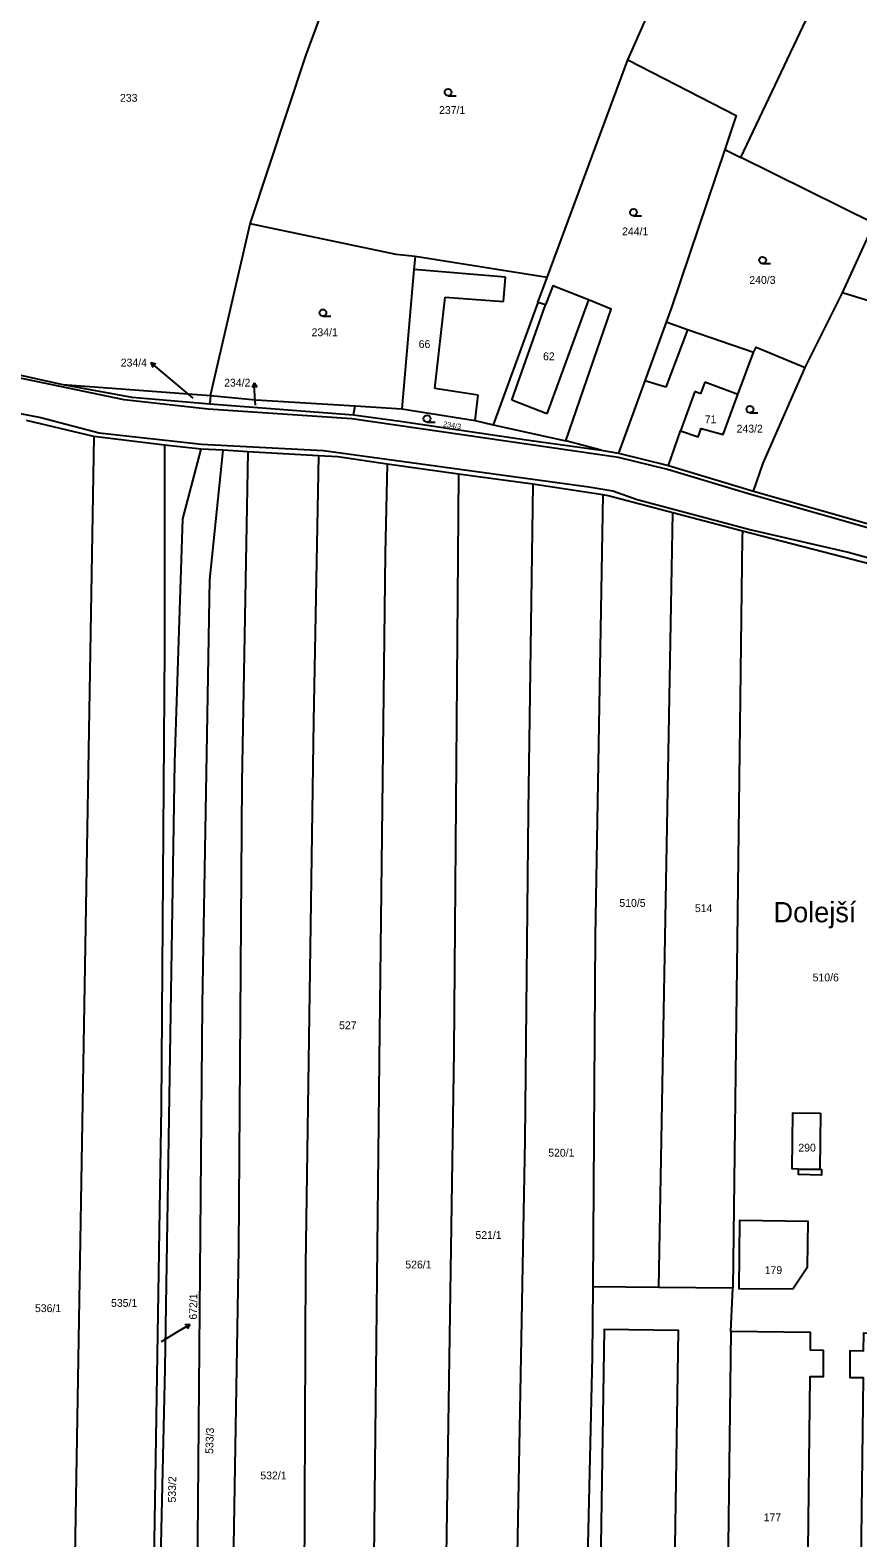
# Model space of a CAD drawing. Extents: x -747333 to -743907, y -1134120 to -1130051.
# Drawn here: x -746642.5 to -746462.8, y -1132539.7 to -1132212.3 of the extents above; entities that cross this region are included whole.
import ezdxf

# ---------------------------------------------------------------- set-up
doc = ezdxf.new("R2010")
doc.units = 0
for name, color, linetype in [('Hranice parcel', 7, 'Continuous'), ('Parcelní čísla', 7, 'Continuous'), ('Pop  PČ popisy', 7, 'Continuous'), ('Vnitřní kresba', 7, 'Continuous'), ('Značky kultur', 7, 'Continuous')]:
    doc.layers.add(name, color=color, linetype=linetype)

msp = doc.modelspace()

# ---------------------------------------------------------------- linework, layer by layer
at = {"layer": 'Hranice parcel'}
for p, q in [((-746512.76, -1132218.71), (-746508.81, -1132209.8)), ((-746530.27, -1132265.98), (-746512.76, -1132218.71)), ((-746491.71, -1132238.23), (-746488.24, -1132239.95)), ((-746459.31, -1132254.28), (-746488.24, -1132239.95)), ((-746603.33, -1132291.63), (-746594.73, -1132254.38)), ((-746466.16, -1132269.31), (-746459.31, -1132254.28)), ((-746530.27, -1132265.98), (-746558.92, -1132261.48)), ((-746532.26, -1132271.42), (-746530.27, -1132265.98)), ((-746532.26, -1132271.42), (-746541.97, -1132298.02)), ((-746474.28, -1132285.54), (-746466.16, -1132269.31)), ((-746438.16, -1132278.12), (-746466.16, -1132269.31)), ((-746488.87, -1132291.4), (-746485.44, -1132282.28)), ((-746635.38, -1132289.23), (-746603.33, -1132291.63)), ((-746603.33, -1132291.63), (-746603.47, -1132293.48)), ((-746603.47, -1132293.48), (-746572.31, -1132295.81)), ((-746572.31, -1132295.81), (-746571.94, -1132293.89)), ((-746571.94, -1132293.89), (-746561.85, -1132294.55)), ((-746628.68, -1132300.58), (-746643.27, -1132297.04)), ((-746541.97, -1132298.02), (-746526.21, -1132301.5)), ((-746613.37, -1132302.42), (-746628.68, -1132300.58)), ((-746518.52, -1132303.5), (-746526.21, -1132301.5)), ((-746503.94, -1132306.81), (-746501.31, -1132299.32)), ((-746605.37, -1132303.28), (-746613.37, -1132302.42)), ((-746600.59, -1132303.55), (-746605.37, -1132303.28)), ((-746595.23, -1132303.86), (-746600.59, -1132303.55)), ((-746579.9, -1132304.75), (-746595.23, -1132303.86)), ((-746518.52, -1132303.5), (-746514.75, -1132304.17)), ((-746514.75, -1132304.17), (-746503.94, -1132306.81)), ((-746549.55, -1132308.74), (-746564.99, -1132306.52)), ((-746503.94, -1132306.81), (-746485.44, -1132312.39)), ((-746533.39, -1132310.87), (-746549.55, -1132308.74)), ((-746518.2, -1132313.24), (-746533.39, -1132310.87)), ((-746506, -1132485.37), (-746503.02, -1132317.1)), ((-746487.88, -1132321.09), (-746503.02, -1132317.1)), ((-746487.88, -1132321.09), (-746487.9, -1132322.49)), ((-746448.07, -1132331.38), (-746487.88, -1132321.09)), ((-746487.9, -1132322.49), (-746489.99, -1132485.51)), ((-746506, -1132485.37), (-746520.37, -1132485.24)), ((-746489.99, -1132485.51), (-746506, -1132485.37)), ((-746490.36, -1132494.89), (-746489.99, -1132485.51)), ((-746490.36, -1132494.89), (-746491.44, -1132579.84))]:
    msp.add_line(p, q, dxfattribs=at)
for points in [[(-746488.24, -1132239.95), (-746463.28, -1132187.24), (-746474.43, -1132179.05), (-746468.85, -1132167.8)], [(-746594.73, -1132254.38), (-746582.55, -1132217.69), (-746573.08, -1132191.94)], [(-746512.76, -1132218.71), (-746489.23, -1132230.86), (-746491.71, -1132238.23)], [(-746491.71, -1132238.23), (-746503.25, -1132272.52), (-746504.41, -1132275.72)], [(-746705.52, -1132254.75), (-746705.52, -1132261.75), (-746702.56, -1132266.68), (-746651.51, -1132285.68), (-746635.38, -1132289.23)], [(-746558.92, -1132261.48), (-746563.06, -1132261.04), (-746594.73, -1132254.38)], [(-746558.92, -1132261.48), (-746559.21, -1132264.29), (-746561.85, -1132294.55)], [(-746526.21, -1132301.5), (-746516.36, -1132272.86), (-746521.29, -1132270.9), (-746529.01, -1132267.83), (-746530.64, -1132271.97), (-746532.26, -1132271.42)], [(-746504.41, -1132275.72), (-746509.03, -1132288.43), (-746514.75, -1132304.17)], [(-746485.44, -1132282.28), (-746499.8, -1132277.41), (-746504.41, -1132275.72)], [(-746485.44, -1132282.28), (-746484.89, -1132281.12), (-746474.28, -1132285.54)], [(-746485.44, -1132312.39), (-746483.4, -1132306.31), (-746474.28, -1132285.54)], [(-746635.38, -1132289.23), (-746620.4, -1132292.04), (-746603.47, -1132293.48)], [(-746603.33, -1132291.63), (-746593.54, -1132292.56), (-746571.94, -1132293.89)], [(-746501.31, -1132299.32), (-746497.49, -1132300.63), (-746496.87, -1132298.83), (-746492.06, -1132300.12), (-746488.87, -1132291.4)], [(-746561.85, -1132294.55), (-746545.91, -1132297.08), (-746541.97, -1132298.02)], [(-746572.31, -1132295.81), (-746562.17, -1132297.22), (-746534.28, -1132301.35), (-746518.52, -1132303.5)], [(-746628.68, -1132300.58), (-746631.28, -1132453.79), (-746633.28, -1132573.72), (-746635.22, -1132678.03)], [(-746613.37, -1132302.42), (-746613.37, -1132346.68), (-746614.08, -1132446.06), (-746615.66, -1132545), (-746618.65, -1132675.35)], [(-746617.07, -1132675.21), (-746613.21, -1132502.87), (-746611.08, -1132371.37), (-746609.37, -1132318.4), (-746605.37, -1132303.28)], [(-746608.92, -1132673.97), (-746606.11, -1132540.09), (-746605.1, -1132423.88), (-746603.53, -1132331.66), (-746600.59, -1132303.55)], [(-746595.23, -1132303.86), (-746596.54, -1132375.65), (-746597.26, -1132477.01), (-746599.26, -1132593.08), (-746600.75, -1132672.72)], [(-746579.9, -1132304.75), (-746580.99, -1132362.37), (-746582.7, -1132480.44), (-746582.99, -1132549.96)], [(-746564.99, -1132306.52), (-746575.68, -1132304.99), (-746579.9, -1132304.75)], [(-746564.99, -1132306.52), (-746565.43, -1132325.98), (-746566.71, -1132436.04), (-746568.01, -1132557.67)], [(-746549.55, -1132308.74), (-746550.51, -1132434.05), (-746552.94, -1132591.21), (-746553.66, -1132645.75), (-746554.56, -1132665.67)], [(-746533.39, -1132310.87), (-746534.4, -1132381.92), (-746535.13, -1132453.3), (-746537.98, -1132610.05), (-746539.11, -1132663.31)], [(-746518.2, -1132313.24), (-746519.81, -1132409.04), (-746520.37, -1132485.24)], [(-746503.02, -1132317.1), (-746517.02, -1132313.41), (-746518.2, -1132313.24)], [(-746485.44, -1132312.39), (-746451.58, -1132322.02), (-746446.14, -1132322.78), (-746443.16, -1132323.2), (-746427.94, -1132325.8)], [(-746470.9, -1132447.53), (-746471.04, -1132459.69), (-746470.74, -1132459.72), (-746470.7, -1132460.94), (-746475.69, -1132460.82), (-746475.68, -1132459.65), (-746477.09, -1132459.62), (-746476.95, -1132447.46), (-746470.9, -1132447.53)], [(-746476.94, -1132485.69), (-746473.77, -1132480.86), (-746473.64, -1132471.05), (-746488.48, -1132470.84), (-746488.65, -1132485.59), (-746476.94, -1132485.69)], [(-746520.37, -1132485.24), (-746520.49, -1132500.34), (-746523.05, -1132610.33)], [(-746519.46, -1132597.46), (-746503.32, -1132597.69), (-746501.74, -1132494.74), (-746517.87, -1132494.47), (-746519.46, -1132597.46)], [(-746491.44, -1132579.84), (-746474.02, -1132580.06), (-746473.18, -1132504.68), (-746470.3, -1132504.71), (-746470.29, -1132499.03), (-746473.11, -1132499), (-746473.07, -1132495.14), (-746490.36, -1132494.89)], [(-746444.3, -1132495.53), (-746461.6, -1132495.32), (-746461.63, -1132499.17), (-746464.54, -1132499.14), (-746464.56, -1132504.89), (-746461.68, -1132504.91), (-746462.63, -1132580.24), (-746445.35, -1132580.44)]]:
    msp.add_lwpolyline(points, dxfattribs=at)
at = {"layer": 'Pop  PČ popisy'}
for p, q in [((-746613.99, -1132286.43), (-746616.289, -1132284.501)), ((-746616.289, -1132284.501), (-746615.2, -1132284.761)), ((-746616.289, -1132284.501), (-746615.844, -1132285.528)), ((-746607.12, -1132292.2), (-746613.99, -1132286.43)), ((-746593.867, -1132288.863), (-746594.315, -1132289.889)), ((-746593.71, -1132291.86), (-746593.867, -1132288.863)), ((-746593.867, -1132288.863), (-746593.315, -1132289.837)), ((-746593.62, -1132293.75), (-746593.71, -1132291.86)), ((-746613.98, -1132497.11), (-746610.41, -1132494.95)), ((-746610.41, -1132494.95), (-746607.838, -1132493.404)), ((-746607.838, -1132493.404), (-746608.954, -1132493.491)), ((-746607.838, -1132493.404), (-746608.438, -1132494.349))]:
    msp.add_line(p, q, dxfattribs=at)
at = {"layer": 'Vnitřní kresba'}
for p, q in [((-746539.29, -1132265.97), (-746559.21, -1132264.29)), ((-746539.74, -1132271.23), (-746539.29, -1132265.97)), ((-746554.68, -1132290.1), (-746552.39, -1132270.27)), ((-746552.39, -1132270.27), (-746539.74, -1132271.23)), ((-746537.96, -1132292.69), (-746530.64, -1132271.97)), ((-746521.29, -1132270.9), (-746530.34, -1132295.65)), ((-746499.8, -1132277.41), (-746504.5, -1132289.85)), ((-746622.06, -1132292.55), (-746651.99, -1132286.34)), ((-746504.5, -1132289.85), (-746509.03, -1132288.43)), ((-746496.04, -1132288.78), (-746496.95, -1132291.26)), ((-746488.87, -1132291.4), (-746496.04, -1132288.78)), ((-746545.21, -1132291.58), (-746554.68, -1132290.1)), ((-746545.91, -1132297.08), (-746545.21, -1132291.58)), ((-746498.22, -1132290.8), (-746501.31, -1132299.32)), ((-746496.95, -1132291.26), (-746498.22, -1132290.8)), ((-746659.25, -1132292.71), (-746640.22, -1132296.44)), ((-746603.86, -1132294.62), (-746622.06, -1132292.55)), ((-746572.69, -1132296.69), (-746603.86, -1132294.62)), ((-746530.34, -1132295.65), (-746537.96, -1132292.69)), ((-746640.22, -1132296.44), (-746627.53, -1132299.75)), ((-746514.76, -1132305.1), (-746572.69, -1132296.69)), ((-746627.53, -1132299.75), (-746605.32, -1132302.23)), ((-746605.32, -1132302.23), (-746578.84, -1132303.61)), ((-746578.84, -1132303.61), (-746521.19, -1132311.48)), ((-746504.14, -1132307.72), (-746514.76, -1132305.1)), ((-746485.8, -1132313.24), (-746504.14, -1132307.72)), ((-746521.19, -1132311.48), (-746516.04, -1132312.33)), ((-746516.04, -1132312.33), (-746510.71, -1132314.23)), ((-746510.71, -1132314.23), (-746485.99, -1132320.82)), ((-746450.49, -1132323.31), (-746485.8, -1132313.24)), ((-746485.99, -1132320.82), (-746464.89, -1132325.65)), ((-746464.89, -1132325.65), (-746447.83, -1132330.31)), ((-746475.68, -1132459.65), (-746471.04, -1132459.69))]:
    msp.add_line(p, q, dxfattribs=at)
at = {"layer": 'Značky kultur'}
for p, q in [((-746551.763, -1132226.54), (-746550.013, -1132226.54)), ((-746511.533, -1132252.63), (-746509.783, -1132252.63)), ((-746483.503, -1132263.01), (-746481.753, -1132263.01)), ((-746578.963, -1132274.43), (-746577.213, -1132274.43)), ((-746486.253, -1132295.39), (-746484.503, -1132295.39)), ((-746556.333, -1132297.41), (-746554.583, -1132297.41))]:
    msp.add_line(p, q, dxfattribs=at)
for centre in [(-746551.763, -1132225.79), (-746511.533, -1132251.88), (-746483.503, -1132262.26), (-746578.963, -1132273.68), (-746486.253, -1132294.64), (-746556.333, -1132296.66)]:
    msp.add_circle(centre, 0.75, dxfattribs=at)

# ---------------------------------------------------------------- texts
at = {"layer": 'Parcelní čísla'}
for s, p in [('233', (-746623, -1132227.85)), ('237/1', (-746553.74, -1132230.5)), ('244/1', (-746514, -1132256.85)), ('240/3', (-746486.38, -1132267.4)), ('234/1', (-746581.41, -1132278.76)), ('66', (-746558.16, -1132281.33)), ('62', (-746531.16, -1132283.99)), ('234/4', (-746622.836, -1132285.35)), ('234/2', (-746600.386, -1132289.71)), ('71', (-746496.05, -1132297.66)), ('243/2', (-746489.14, -1132299.7)), ('510/5', (-746514.59, -1132402.7)), ('514', (-746498.2, -1132403.84)), ('510/6', (-746472.63, -1132418.88)), ('527', (-746575.44, -1132429.27)), ('520/1', (-746530.04, -1132456.95)), ('290', (-746475.734, -1132455.84)), ('521/1', (-746545.84, -1132474.82)), ('526/1', (-746561.06, -1132481.23)), ('179', (-746483.04, -1132482.44)), ('535/1', (-746624.94, -1132489.57)), ('536/1', (-746641.46, -1132490.71)), ('532/1', (-746592.53, -1132527.04)), ('177', (-746483.26, -1132536.13))]:
    msp.add_text(s, height=1.7, dxfattribs=at).set_placement(p)
for s, height, rotation, p in [('234/3', 1.14, 351, (-746552.926, -1132298.362)), ('672/1', 1.7, 89, (-746606.3, -1132492.364)), ('533/3', 1.7, 88, (-746602.79, -1132521.519)), ('533/2', 1.7, 89, (-746610.89, -1132532.074))]:
    msp.add_text(s, height=height, rotation=rotation, dxfattribs=at).set_placement(p)
at = {"layer": 'Pop  PČ popisy'}
msp.add_text('Dolejší', height=4.4, dxfattribs=at).set_placement((-746481.118, -1132406.05))

doc.saveas('drawing.dxf')
